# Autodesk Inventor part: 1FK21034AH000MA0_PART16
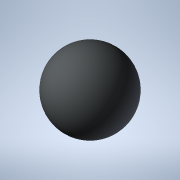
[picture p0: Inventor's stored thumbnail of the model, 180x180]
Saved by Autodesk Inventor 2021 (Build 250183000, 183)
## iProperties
Created: 2025-04
Part Number: 1FK21034AH000MA0_PART16
Material: Generic
Catalog Web Link: www.3dfindit.com
Description: -Servo synchronous motor
Document SubType Name: Modeling
Designer: psAdmin
Mass: 0.113097 g
Surface Area: 1.13097 cm^2
Volume: 0.113097 cm^3
Density: 1 g/cm^3
Appearance: PSOLRGB-212-217-219
Category: PARTsolutions
Title: 1FK21034AH000MA0_PART16
Author: Cadenas PARTsolutions
Comments: Servo synchronous motor
Sending System: PARTsolutions
Preprocessor: ST-DEVELOPER v19.3
PSOL_IDENT_0: {$CADENAS_DATA/23d-libs/siemens_ag/_cat_/ec/b7/1fk21034ah000ma0.prj},216 {VTYP=3D},{NB=1FK21034AH000
PSOL_IDENT_1: MA0_PART16},{LINA=1FK21034AH000MA0_PART16},{NN=1FK21034AH000MA0_PART16},{NOPRJ=TRUE},{DATE=19.08.202
PSOL_IDENT_2: 5 14:01:05},{GEOMDATE=30.07.2025 02:01:02},{VERSION=},{LINEID=10},{WBVAR=},{WBNUMERIC=}  {NB=1FK2103
PSOL_IDENT_3: 4AH000MA0_PART16},{LINA=1FK21034AH000MA0_PART16},{KT=DUMMY},{PREVIEW=../../../_pool_/7c/50/p_d211_xx
PSOL_IDENT_4: _00932j.png},{DESCSHORT=SIMOTICS S-1FK2 HD, SINAMICS S210 3AC 400V-480V, 1.01 Nm, 4500 rpm},{DESCLON
PSOL_IDENT_5: G=SIMOTICS S-1FK2 HD servo motor M0=1.27 Nm; PN = 0.48 kW at nN=4500 rpm (380-480 V); PN = 0.3 kW at
PSOL_IDENT_6: nN=2500 rpm (200-240 V); degree of protection IP64; cylindrical shaft D14 x 30 mm; absolute encoder
PSOL_IDENT_7: 22-bit + 12-bit multiturn (encoder AM22DQC); with OCC interface; plug size M17, rotatable; SIMOTICS
PSOL_IDENT_8: S-1FK2 servomotorfor a wide range of uses in industrial environments. SIMOTICS S‑1FK2 servomotors a
PSOL_IDENT_9: re compact synchronous motors with a high dynamic performance that set themselves apart as a result
PSOL_IDENT_10: of their high power density, degree of protection and overload capability. The motors are available
PSOL_IDENT_11: in two variants: as High Dynamic variant (highest dynamic performance as a result of the low intrins
PSOL_IDENT_12: ic moment of inertia for applications demanding a high dynamic performance with low moved masses) -
PSOL_IDENT_13: and as Compact variant (precise and stable closed-loop control for medium up to large moved masses a
PSOL_IDENT_14: s a result of a medium intrinsic moment of inertia). SIMOTICSS‑1FK2 servomotors fully exploit their
PSOL_IDENT_15: strengths in a system with the SINAMICSS210 frequency converter and simple connection using the one
PSOL_IDENT_16: cable connection (OCC). Advantages include the short control and positioning times, fast and precise
PSOL_IDENT_17: correction of disturbing quantities as well as stable control with a high dynamic performance. The
PSOL_IDENT_18: servo motors can be configured to address a wide range of requirements. For example with and without
PSOL_IDENT_19: holding brake, IP64 or IP65 degree of protection, singleturn or multiturn absolute encoders - to na
PSOL_IDENT_20: me just a few. Further, the servomotors are available in different shaft heights extending from 20 t
PSOL_IDENT_21: o 100. A shaft sealing ring is available to achieve an IP65 degree of protection and for subsequent
PSOL_IDENT_22: mounting at the motor or as spare part. SIMOTICS - the optimum motor for each and every motion contr
PSOL_IDENT_23: ol application.},{INTNO=4034106444822},{SUPPLIERALTNO=1FK2103-4AH00-0MA0},{MANUID=1FK21034AH000MA0},
PSOL_IDENT_24: {MANUNAME=Siemens},{MANUTYPEDESC=SYNCHRONOUS MOTOR 1FK2 HD 1,27 NM},{AAU732=SIMOTICS},{AAO057=S-1FK2
PSOL_IDENT_25: },{AAU734=SIMOTICS S-1FK2 HD servo motor M0=1.27 Nm; PN = 0.48 kW at nN=4500 rpm (380-480 V); PN = 0
PSOL_IDENT_26: .3 kW at nN=2500 rpm (200-240 V); degree of protection IP64; cylindrical shaft D14 x 30 mm; absolute
PSOL_IDENT_27: encoder 22-bit + 12-bit multiturn (encoder AM22DQC); with OCC interface; plug size M17, rotatable;}
PSOL_IDENT_28: ,{AAW338=SYNCHRONOUS MOTOR 1FK2 HD 1,27 NM},{AAO742=SIMOTICS},{AAO663=4034106444822},{NOCUPEROU=1},{
PSOL_IDENT_29: PRICEQUANTITY=1},{QUANTITYMIN=1},{QUANTITYINT=1},{CTN=85015100},{COO=RO},{AAO676=1FK2103-4AH00-0MA0}
PSOL_IDENT_30: ,{AAO677=Siemens AG},{ORDERUNIT=C62},{CONTENTUNIT=C62}
NB: 1FK21034AH000MA0_PART16
NT: Servo synchronous motor
NBSYN: $MANUID._PART16
LINA: 1FK21034AH000MA0_PART16
CATALOG: SIEMENS
PREVIEW: ../../../_pool_/7c/50/p_d211_xx_00932j.png
DESCSHORT: SIMOTICS S-1FK2 HD, SINAMICS S210 3AC 400V-480V, 1.01 Nm, 4500 rpm
DESCLONG: SIMOTICS S-1FK2 HD servo motor M0=1.27 Nm; PN = 0.48 kW at nN=4500 rpm (380-480 V); PN = 0.3 kW at nN=2500 rpm (200-240 V); degree of protection IP64; cylindric
INTNO: 4034106444822
SUPPLIERALTNO: 1FK2103-4AH00-0MA0
MANUID: 1FK21034AH000MA0
MANUNAME: Siemens
MANUTYPEDESC: SYNCHRONOUS MOTOR 1FK2 HD 1,27 NM
AAU732: SIMOTICS
AAO057: S-1FK2
AAU734: SIMOTICS S-1FK2 HD servo motor M0=1.27 Nm; PN = 0.48 kW at nN=4500 rpm (380-480 V); PN = 0.3 kW at nN=2500 rpm (200-240 V); degree of protection IP64; cylindric
AAW338: SYNCHRONOUS MOTOR 1FK2 HD 1,27 NM
AAO742: SIMOTICS
AAO663: 4034106444822.0
NOCUPEROU: 1
PRICEQUANTITY: 1
QUANTITYMIN: 1
QUANTITYINT: 1
CTN: 85015100
COO: RO
ARTICLENO: 1FK21034AH000MA0_PART16
BOMINFO: 1FK21034AH000MA0_PART16
CREATOR: CADENAS GmbH
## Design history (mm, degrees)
feature "2025_04_17_15_01_37_0314"
body "Solid1"
